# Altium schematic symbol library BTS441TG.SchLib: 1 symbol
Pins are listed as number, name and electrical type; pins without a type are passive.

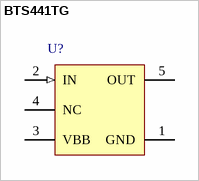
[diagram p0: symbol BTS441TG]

## BTS441TG
designator U?
Smart Power High-Side-Switch, 1 Channel, 17 A Load Current, -40 to 150 degC, PG-TO263-5-2, Reel, Green; Manufacturer: Infineon; PartNumber: BTS441TG; Channels: 1; Green: TRUE; Group: Automotive Qualified; Load Current (typ): 17 A; Ptot (max): 125 W; Recommended Operating Voltage Max.: 41 V; Recommended Operating Voltage Min.: 4.75 V; RON @ 25degreesC: 20 mOhm; RON(max) @ 150degreesC: 37 mOhm; toff (max): 250 us; ton (max): 200 us
footprint INF-PG-TO263-5-2_N (DPAK, 5-Leads, Body 10x9.25mm, Pitch 1.7mm, IPC Medium Density)
footprint INF-PG-TO263-5-2_L (DPAK, 5-Leads, Body 10x9.25mm, Pitch 1.7mm, IPC High Density)
footprint INF-PG-TO263-5-2_M (DPAK, 5-Leads, Body 10x9.25mm, Pitch 1.7mm, IPC Low Density)
pins: 1 GND (power) "Logic ground.", 2 IN (in) "Input, activates the power switch in case of logical high signal.", 3 VBB (power) "Positive power supply voltage.", 4 NC "Not connected.", 5 OUT (power) "Output to the load."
